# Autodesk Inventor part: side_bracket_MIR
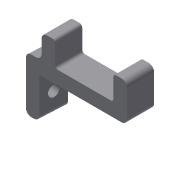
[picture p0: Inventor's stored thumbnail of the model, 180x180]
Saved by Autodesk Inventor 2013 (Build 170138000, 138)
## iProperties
Created: 2013-11
Part Number: side_bracket_MIR
Material: Generic
Document SubType Name: Modeling
Designer: Jonas
Density: 1 g/cm^3
Author: Jonas
d0: 87,00 deg
d1: 36,741 mm
d7: 10,000 mm
d8: 5,000 mm
d9: 0,00 deg
d10: 5,000 mm
d11: 5,000 mm
d12: 21,500 mm
d13: 9,000 mm
d14: 0,00 deg
d18: 5,000 mm
d19: 15,000 mm
d20: 0,00 deg
d21: 4,000 mm
d28: 2,000 mm
d29: 1,000 mm
theta: 3,00 deg
frame_height: 710,000 mm
clearance_top: 400,000 mm
clearance_side: 250,000 mm
side_bracket_padding_top: 100,000 mm
sprocket_N: 18,000 ul
sprocket_wall_clearance: 1,000 mm
ball_diameter: 2,400 mm
ball_distance: 0,820 mm
frame_thickness: 21,500 mm
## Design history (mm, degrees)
derived "side_bracket.ipt"
  sketch "Sketch1"
    geometry: L1 (0, 0)-(-37.265, 0) reference; L2 (-37.265, 0)-(-37.265, 10) reference; L3 (-37.265, 10)-(-0.524, 10) reference; L4 (-0.524, 10)-(0, 0) reference
  sketch "Sketch4"
    geometry: L1 (0, 0)-(-37.265, 0) reference; L2 (-37.265, 10)-(-0.524, 10) reference; L3 (-37.265, 10)-(-32.265, 10) reference; L4 (-32.265, 10)-(-32.265, 0) reference; L5 (-32.265, 0)-(-37.265, 0) reference; L6 (-37.265, 0)-(-37.265, 10) reference; L7 (-10.765, 10)-(-5.765, 10) reference; L8 (-5.765, 10)-(-5.765, 0) reference; L9 (-5.765, 0)-(-10.765, 0) reference; L10 (-10.765, 0)-(-10.765, 10) reference
  sketch "Sketch6"
    geometry: L1 (0, 0)-(37.265, 0) reference; L2 (0.524, 10)-(0, 0) reference; L3 (37.265, 10)-(0.524, 10) reference; L4 (0, 0)-(5, 0) reference; L5 (5, 0)-(5.524, 10) reference; L6 (0.524, 10)-(0, 0) reference
  sketch "Sketch7"
    geometry: L1 (0, 10.014)-(-15, 0) reference; 2 further points
feature "Solid1::side_bracket.ipt"
tag "TaggingFeature1"
body "Solid1"
other parameters: "d0" = 57.2958 deg, "d0_1" = 87 deg, "d1" = 36.74078, "d7" = 10, "d8" = 5, "d9" = 0 deg, "d10" = 5, "d11" = 5, "d12" = 21.5, "d13" = 9, "d14" = 0 deg, "d18" = 5, "d19" = 15, "d20" = 0 deg, "d21" = 4, "d28" = 2, "d29" = 1, "theta" = 3 deg, "frame_height" = 710, "clearance_top" = 400, "clearance_side" = 250, "side_bracket_padding_top" = 100, "sprocket_N" = 18, "sprocket_wall_clearance" = 1, "ball_diameter" = 2.4, "ball_distance" = 0.82, "frame_thickness" = 21.5
